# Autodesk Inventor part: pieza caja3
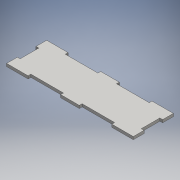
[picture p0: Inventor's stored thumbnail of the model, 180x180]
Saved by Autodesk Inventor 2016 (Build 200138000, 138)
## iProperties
Created: 2016-06
Part Number: pieza caja3
Material: Genérico
Document SubType Name: Modeling
Designer: adm
Density: 1 g/cm^3
Appearance: Valor por defecto
Author: adm
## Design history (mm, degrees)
sketch "Boceto1"
  geometry: L1 (-68, -21.5)-(68, 21.5); L2 (68, -21.5)-(-68, 21.5); L3 (65, 10)-(65, -10); L4 (-65, -10)-(-65, 10); L5 (-10, 21.5)-(-10, 18.5); L6 (10, 21.5)-(10, 18.5); L7 (-45, 21.5)-(-45, 18.5); L8 (10, -21.5)-(10, -18.5); L9 (-10, -21.5)-(-10, -18.5); L10 (45, 21.5)-(45, 18.5); L11 (-45, 21.5)-(-68, 21.5); L12 (68, 21.5)-(45, 21.5); L13 (10, 21.5)-(-10, 21.5); L14 (10, 18.5)-(45, 18.5); L15 (-68, -21.5)-(-45, -21.5); L16 (-10, -18.5)-(-45, -18.5); L17 (-10, -21.5)-(10, -21.5); L18 (45, -21.5)-(68, -21.5); L19 (45, -21.5)-(45, -18.5); L20 (43.731, -13.827)-(43.722, -12.491); L21 (-45, -21.5)-(-45, -18.5); L22 (-46.455, -14.688)-(-46.447, -13.352); L23 (-68, 10)-(-65, 10); L24 (-68, 21.5)-(-68, 10); L25 (-68, -10)-(-68, -21.5); L26 (-68, -10)-(-65, -10); L27 (68, 10)-(65, 10); L28 (68, -10)-(65, -10); L29 (68, -21.5)-(68, -10); L30 (68, 10)-(68, 21.5); L31 (-45, 18.5)-(-10, 18.5); L32 (45, -18.5)-(10, -18.5); 19 further points
  constraints: 64 end point, 20 parallel, 12 perpendicular, 3 horizontal, 3 midpoint, 2 point on line
  dimensions: "d0" = 136 distance of L2.end L1.end; "d14" = 43 distance between parallel lines of L18 L12; "d15" = 43 distance between parallel lines of L15 L11; "d16" = 3 distance between parallel lines of L30 L3; "d17" = 3 distance between parallel lines of L4 L24; "d18" = 3 distance between parallel lines of L25 L4; "d19" = 3 distance between parallel lines of L29 L3; "d20" = 3 distance between parallel lines of L31 L11; "d21" = 35 distance between parallel lines of L5 L7; "d22" = 35 distance between parallel lines of L10 L6; "d23" = 3 distance between parallel lines of L16 L15; "d24" = 23 distance of L1.start L15.end; "d25" = 23 distance of L7.start L2.end; "d26" = 23 distance of L1.end L10.start; "d27" = 20 distance of L9.start L8.start; "d28" = 35 distance of L19.end L8.end; "d29" = 35 distance of L9.end L16.end; "d30" = 23 distance of L18.start L2.start
extrude "Extrusión1" new body sketch "Boceto1" distance "d12" = 3; taper "d13" = 0 deg
node "Sólido1"
other parameters: "d2" = 3, "d5" = 35
